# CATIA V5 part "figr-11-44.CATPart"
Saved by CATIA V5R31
Part number: Part1
Bounding box of the stored display mesh (mm): x -59 to 59, y -60 to 60, z 0 to 39.8
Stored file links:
  D:\PROJECTS\Project 2021\US EDITION\CATIA V5 6R 2021\Resources\Part Files\c11_catia_v5_6r2021_prt\figr-11-44.CATPart
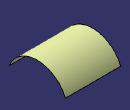
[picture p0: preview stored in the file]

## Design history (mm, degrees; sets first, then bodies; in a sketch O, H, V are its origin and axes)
AxisSystem1: origin (0, 0, 0), X (1, 0, 0), Y (0, 1, 0), Z (0, 0, 1)
AxisSystem2: origin (0, 150, -30), X (1, 0, 0), Y (0, 1, 0), Z (0, 0, 1)
Set1
  Extrude1: Element1 Sketch2, Lim1 59, Lim2 59, Direction yz-plane
  Sketch1 on yz-plane, origin (0, 0, 0), H (0, 1, 0), V (0, 0, 1)
    point P1 (150, -30)
  AxisToAxis1: ToTransfor Extrude1, AxisOrigin AxisSystem1, Axis AxisSystem2
Body1 (main body)
  Sketch2 on yz-plane, origin (0, 0, 0), H (0, 1, 0), V (0, 0, 1)
    arc A1 centre (0, -25) radius 65 from (-60, 0) to (60, 0) cw
    point P2 (-60, 0)
    point P3 (60, 0)
    coincidence: P2 H, P3 H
